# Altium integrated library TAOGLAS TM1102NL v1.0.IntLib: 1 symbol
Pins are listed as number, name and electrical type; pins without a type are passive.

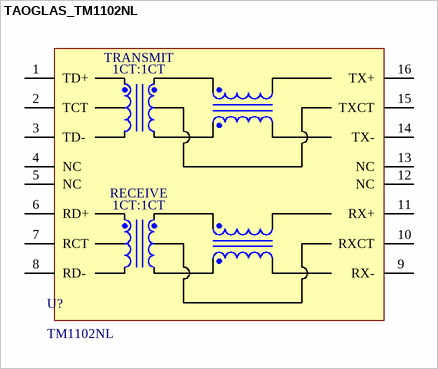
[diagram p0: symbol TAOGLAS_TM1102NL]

## TAOGLAS_TM1102NL
designator U?, comment TM1102NL
10/100 Base-T transformer Single Port and 16pin SMT; ComponentLibStatus: Created; MFG: Taoglas; Temp_High: +85C; Temp_Low: -40C
footprint TAOGLAS_TM1102NL (10/100 Base-T transformer Single Port and 16pin SMT)
pins: 1 TD+, 2 TCT, 3 TD-, 4 NC, 5 NC, 6 RD+, 7 RCT, 8 RD-, 9 RX-, 10 RXCT, 11 RX+, 12 NC, 13 NC, 14 TX-, 15 TXCT, 16 TX+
